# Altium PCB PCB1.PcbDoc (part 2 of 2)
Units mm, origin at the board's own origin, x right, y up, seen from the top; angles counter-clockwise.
Board outline 100 x 100 mm, 2 copper layers (Top Layer, Bottom Layer); 114 components, 82 nets, 496 pads, 121 vias.
Unrouted connection lines stored in the file: 6.
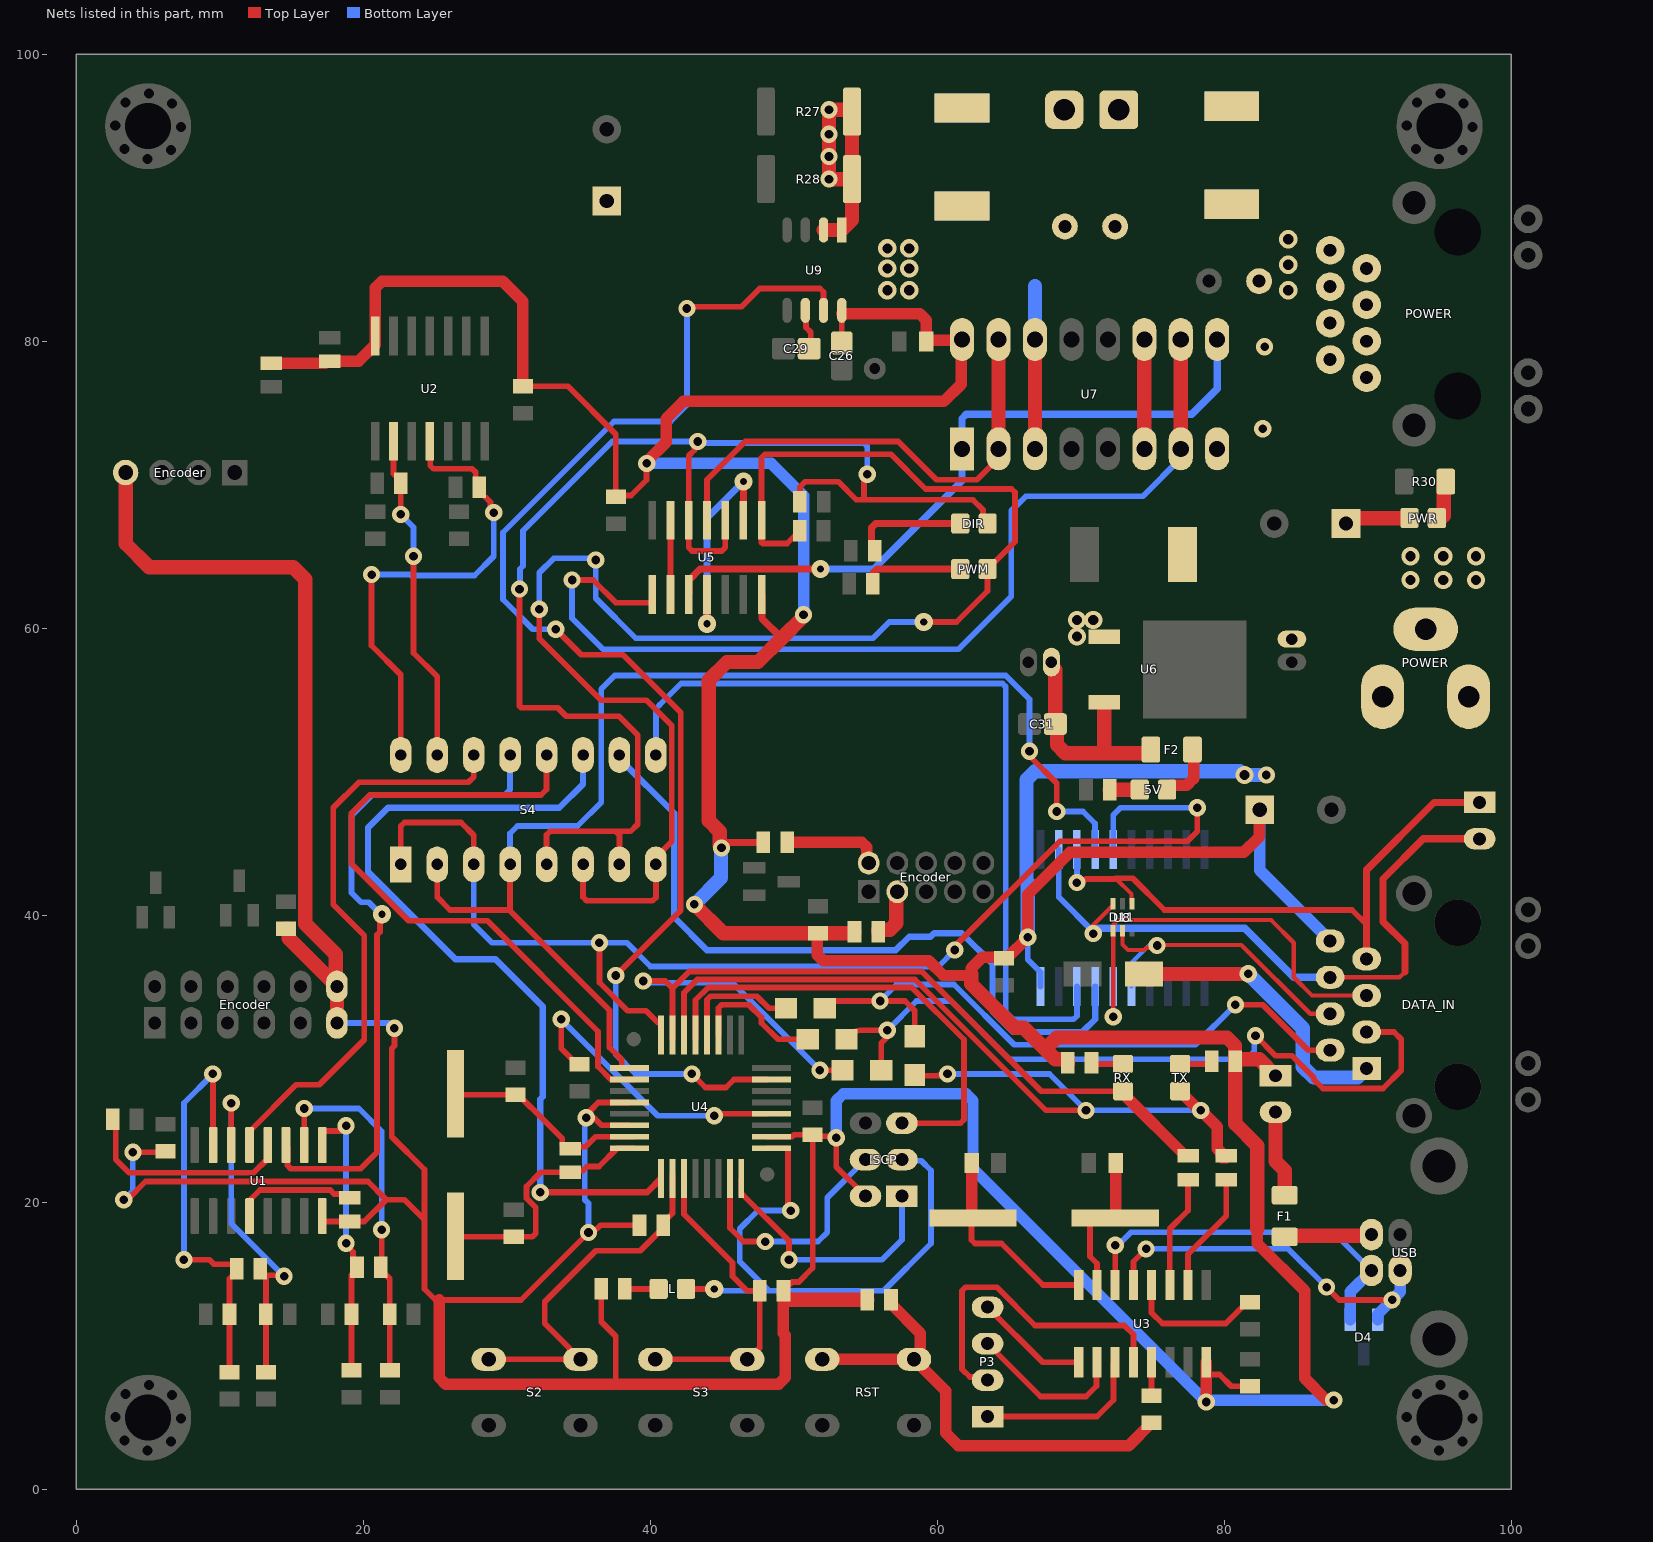
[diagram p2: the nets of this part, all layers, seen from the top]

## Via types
v1: diameter 1.2, hole 0.6, Top Layer to Bottom Layer, 93 vias
v2: diameter 1.27, hole 0.711, Top Layer to Bottom Layer, 22 vias
v3: diameter 1.27, hole 0.5, Top Layer to Bottom Layer, 6 vias

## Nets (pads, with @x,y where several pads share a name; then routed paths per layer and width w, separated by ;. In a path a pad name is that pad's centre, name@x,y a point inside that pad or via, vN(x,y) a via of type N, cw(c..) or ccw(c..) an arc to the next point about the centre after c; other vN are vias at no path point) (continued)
6: 5V.A C1.1 C2.1 C8.1 C12.1 C13.1 C14.1 C21.1 C22.1 C24.1 C25.2 C26.2 DATA_IN.8 Encoder.4@3.429,70.866 Encoder.11 Encoder.12 F2.2 ISCP.2 P4.1 R1.2 R2.1 R3.1 R10.2 R11.2 R13.1 R15.2 R17.1 R18.1 R21.1 R31.1 U1.16 U2.14 U3.16 U4.4 U4.6 U4.18 U5.14 U7.16 U8.20 U9.8 | length 562.9
  Top Layer w0.4: v1(3.302,20.193) 3.556,20.193 4.826,21.463 20.32,21.463 21.59,20.193 ; v1(3.937,23.495) 6.147,23.495 C12.1@6.223,23.571 ; U1.16@17.145,19.05 17.145,18.769 17.245,18.669 R13.1@19.05,18.669 20.066,18.669 21.59,20.193 ; v1(22.164,32.131) 22.164,30.924 21.971,30.731 21.971,24.575 24.257,22.289 24.257,18.796 ; C13.1@31.115,76.886 34.239,76.886 37.592,73.533 C22.1@37.592,69.19 37.666,69.263 38.656,69.263 39.733,70.34 39.733,71.483 v1(39.751,71.501) ; v1@35.433,25.908 v1@35.536,25.908 ; v1(35.536,25.897) v1@35.536,25.908 ; R31.1@36.577,13.97 36.577,11.683 37.592,10.668 37.592,7.332 ; U4.6@38.542,25.371 36.605,25.371 36.068,25.908 v1@35.536,25.908 ; U4.4@38.542,26.971 36.369,26.971 36.086,26.688 36.086,26.663 35.536,26.113 v1@35.536,25.908 ; R18.1@39.243,18.415 36.52,18.415 36.012,17.907 v1(35.687,17.907) 30.988,13.208 25.273,13.208 25.019,13.208 24.257,13.97 24.257,18.796 ; U4.18@48.142,24.571 U4.18@48.442,24.571 49.866,24.571 50.01,24.714 C14.1@51.308,24.714 ; R21.1@49.55,14.293 49.725,14.293 49.891,14.459 50.34,14.459 51.308,15.427 C14.1@51.308,24.714 ; C26.2@53.34,79.894 U9.8@53.34,81.941 ; U9.8@53.34,82.157 U9.8@53.34,82.169 ; ISCP.2@54.991,20.447 52.959,22.479 v1(52.959,24.511) 52.857,24.613 51.41,24.613 C14.1@51.308,24.714 ; U3.16@78.74,8.13 78.858,8.012 79.662,8.012 80.485,7.188 C8.1@81.788,7.188 ; 21.59,20.193 22.86,20.193 24.257,18.796
  Top Layer w0.5: v1@44.942,44.688 v1(44.958,44.704) 45.339,45.085 R1.2@47.879,45.085 ; U5.14@47.752,62.357 47.769,62.34 47.769,60.689 49.149,59.309
  Top Layer w0.8: R15.2@13.589,78.485 17.35,78.485 17.478,78.613 R11.2@17.653,78.613 19.663,78.613 20.828,79.778 U2.14@20.828,80.378 20.828,83.732 21.297,84.201 29.718,84.201 31.115,82.804 C13.1@31.115,76.886 ; 25.273,13.208 25.273,7.801 25.742,7.332 37.592,7.332 48.934,7.332 49.403,7.801 49.403,10.747 49.275,10.875 49.275,13.618 R21.1@49.275,13.843 ; v1(39.751,71.501) 39.751,71.636 41.098,72.983 41.098,74.626 42.291,75.819 60.452,75.819 61.658,77.025 61.658,80.073 C21.1@59.296,80.073 ; C2.1@51.689,38.76 51.688,38.759 51.688,38.703 51.637,38.652 51.637,37.244 52.045,36.836 59.399,36.836 60.421,35.814 62.357,35.814 ; U9.8@53.34,81.941 58.764,81.941 59.233,81.472 C21.1@59.233,80.01 ; 62.357,35.91 62.357,36.322 63.119,37.084 64.465,37.084 64.592,36.957 C25.2@64.643,37.008 64.834,37.008 66.294,38.468 v1(66.294,38.481) 66.294,41.456 69.237,44.399 81.356,44.399 82.423,45.466 82.423,47.331 C24.1@82.463,47.371 ; 5V.A@76.01,48.768 76.01,48.833 76.244,49.068 77.382,49.068 77.851,49.537 77.851,51.488 F2.2@77.777,51.562 ; v1(78.74,6.096) 78.74,8.13 U3.16@78.74,8.862 ; 82.296,18.161 82.296,17.145 85.598,13.843 85.598,7.747 87.122,6.223 v1(87.63,6.223)
  Top Layer w1: Encoder.4@3.28,70.717 Encoder.4@3.429,70.866 3.429,65.913 5.08,64.262 15.113,64.262 15.954,63.421 15.954,39.418 18.07,37.302 Encoder.12@18.07,35.143 ; C1.1@14.605,39.065 14.795,39.065 14.803,39.057 14.803,38.41 Encoder.12@18.07,35.143 ; Encoder.11@18.161,32.512 Encoder.12@18.161,35.052 Encoder.12@18.07,35.143 ; v1(43.069,40.767) 45.077,38.759 C2.1@51.688,38.759 ; v1(44.958,44.704) 44.958,44.758 44.843,44.873 44.843,45.835 44.069,46.609 44.069,56.388 45.339,57.658 47.498,57.658 49.149,59.309 50.673,60.833 v1(50.673,60.96) ; R21.1@49.275,13.618 49.685,13.208 R17.1@55.118,13.208 ; C2.1@51.689,38.76 54.204,38.76 54.229,38.785 R10.2@54.229,38.862 ; 62.357,35.91 62.357,35.814 62.357,35.218 65.407,32.168 66.012,32.168 68.211,29.968 69.064,29.968 69.089,29.943 R3.1@69.089,29.718 ; 67.836,31.006 68.326,31.496 80.186,31.496 80.746,30.936 80.746,29.87 R2.1@80.771,29.845 ; 82.296,18.161 82.296,23.959 80.771,25.484 R2.1@80.771,29.845 ; P4.1@83.566,28.829 82.423,29.972 80.796,29.972 80.771,29.947 R2.1@80.771,29.845
  Bottom Layer w0.4: v1(3.302,20.193) 3.937,20.828 v1(3.937,23.495) ; Encoder.11@18.161,32.512 v1@21.736,32.512 ; v1(35.536,25.897) 35.433,25.794 35.433,20.193 35.687,19.939 v1(35.687,17.907) ; v1(66.294,38.481) 66.294,36.924 67.183,36.035 U8.20@67.183,35.052
  Bottom Layer w0.8: v1(39.751,71.501) 48.426,71.501 50.673,69.254 v1(50.673,60.96) ; v1(52.959,24.511) 52.959,27.09 53.428,27.559 62.015,27.559 62.484,27.09 62.484,22.352 v1(78.74,6.096) 78.867,6.223 v1(87.63,6.223) ; C24.1@82.463,47.371 82.463,43.14 DATA_IN.8@87.376,38.227
  Bottom Layer w1: v1(43.069,40.767) 44.92,42.618 44.92,44.666 v1(44.958,44.704) ; v1(66.294,38.481) 66.294,42.309 66.216,42.387 66.216,49.452 66.802,50.038 81.08,50.038 81.334,49.784 v2(81.407,49.784) v1(82.931,49.784)
A+: C5.1 R6.2 R9.2 U1.1 | length 20.2
  Top Layer w0.4: U1.1@17.145,24 17.145,24.875 17.245,24.975 18.371,24.975 18.602,25.206 18.659,25.206 v1(18.796,25.343) ; v1(18.796,17.154) 18.796,17.037 19.284,16.549 19.284,15.594 19.559,15.319 19.177,14.937 R6.2@19.177,12.192 C5.1@19.177,8.306
  Bottom Layer w0.4: v1(18.796,17.154) v1(18.796,25.343)
A-: C6.1 R7.1 R9.1 U1.2 | length 25.5
  Top Layer w0.4: U1.2@15.875,24 v1(15.875,26.543) ; v1(21.273,18.098) 21.273,15.382 21.209,15.319 21.845,14.683 R7.1@21.845,12.192 C6.1@21.844,8.306 C6.1@21.844,8.306
  Bottom Layer w0.4: v1(15.875,26.543) 19.685,26.543 21.273,24.956 v1(21.273,18.098)
B+: C3.1 R4.2 R8.2 U1.7 | length 30.1
  Top Layer w0.4: v1(7.493,16.002) 9.271,16.002 9.573,15.7 10.901,15.7 11.176,15.425 11.176,15.192 10.667,14.683 R4.2@10.667,12.192 C3.1@10.668,8.179 C3.1@10.668,8.179 ; v1(9.506,28.956) 9.516,28.947 9.516,24.009 U1.7@9.525,24
  Bottom Layer w0.4: v1(7.493,16.002) 7.493,26.924 9.506,28.937 v1(9.506,28.956)
B-: C4.1 R5.2 R8.1 U1.6 | length 25.3
  Top Layer w0.4: U1.6@10.795,24 v1(10.795,26.924) ; R8.1@12.826,15.367 12.826,15.192 R8.1@13.101,14.917 ; C4.1@13.208,8.179 C4.1@13.208,8.179 R5.2@13.209,12.192 13.209,14.809 R8.1@13.101,14.917 ; v1(14.478,14.859) 14.42,14.917 R8.1@13.101,14.917
  Bottom Layer w0.4: v1(10.795,26.924) 10.795,18.542 v1(14.478,14.859)
D: "Dir - Pulse.2" D11.3 DATA_IN.6 U8.2 | length 48
  Top Layer w0.2: D11.3@72.173,40.64 72.248,40.715 D11.3@72.248,40.828
  Top Layer w0.3: v1(70.866,38.735) 70.866,39.333 D11.3@72.173,40.64 ; DATA_IN.6@87.376,35.687 92.202,35.687 92.583,36.068
  Top Layer w0.5: 92.583,36.068 92.583,38.036 91.059,39.56 91.059,42.545 93.853,45.339 97.79,45.339
  Bottom Layer w0.4: U8.2@68.453,44.602 68.453,41.275 70.866,38.862 v1(70.866,38.735)
  Bottom Layer w0.5: v1(70.866,38.735) 71.235,39.104 81.419,39.104 84.836,35.687 DATA_IN.6@87.376,35.687
Data_1: DATA_IN.3 R32.1 R35.1 | length 52.6
  Top Layer w0.4: R32.1@53.674,31.369 54.018,31.713 cw(c54.731,31.003) 54.605,32.001 cw(c54.654,31.604) 54.654,32.004 v1(56.515,32.004) 56.515,31.543 56.087,31.115 R35.1@56.087,29.21 ; v1(82.169,31.623) 83.566,30.226 84.709,30.226 86.233,28.702 86.233,28.575 86.868,27.94 91.059,27.94 92.329,29.21 92.329,31.369 91.821,31.877 DATA_IN.3@89.916,31.877
  Bottom Layer w0.4: v1(56.515,32.004) 58.547,34.036 60.96,34.036 65.024,29.972 81.534,29.972 82.085,30.523 82.085,31.539 v1(82.169,31.623)
Data_2: DATA_IN.2 R33.1 R34.1 | length 44.6
  Top Layer w0.4: R34.1@52.15,33.528 52.658,34.036 v1(56.007,34.036) 57.743,34.036 58.42,33.359 R33.1@58.42,31.576 ; v1(80.772,33.782) 82.677,33.782 85.852,30.607 DATA_IN.2@87.376,30.607
  Bottom Layer w0.4: v1(56.007,34.036) 57.15,35.179 61.167,35.179 65.358,30.988 77.978,30.988 v1(80.772,33.782)
Dir: DIR.A R23.1 S4.5 S4.7 U5.3 U5.5 | length 96.9
  Top Layer w0.4: v1(30.88,62.743) 30.88,54.603 31.007,54.476 33.547,54.476 34.143,53.88 37.814,53.88 39.116,52.578 39.116,46.355 38.619,45.858 37.581,45.858 ; S4.5@32.766,43.561 32.766,45.623 33,45.858 37.581,45.858 ; S4.7@37.846,43.561 37.846,45.593 37.581,45.858 ; v1(43.307,73.025) 43.077,72.795 43.077,72.433 42.672,72.028 42.672,65.639 42.906,65.405 44.978,65.405 45.212,65.639 U5.3@45.212,66.98 ; R23.1@50.42,68.834 50.42,69.851 50.8,70.231 53.086,70.231 54.356,68.961 54.737,68.961 ; v1(55.118,70.739) 54.888,70.509 54.888,69.112 54.737,68.961 ; DIR.A@63.5,67.31 63.172,67.638 63.172,68.273 62.484,68.961 54.737,68.961
  Bottom Layer w0.4: v1(30.88,62.743) 30.922,62.785 30.922,64.143 31.122,64.343 31.122,66.809 37.338,73.025 v1(43.307,73.025) 43.403,72.929 54.884,72.929 55.118,72.695 v1(55.118,70.739)
Dir2: U5.6 U5.9 | length 5.2
  Top Layer w0.4: U5.9@41.402,62.357 U5.6@41.402,67.539
Dir_D: S4.10 U8.17 | length 51.1
  Bottom Layer w0.444: S4.10@37.846,51.181 37.846,50.927 41.656,47.117 41.656,39.871 43.94,37.587 57.109,37.587 58.041,38.519 59.525,38.519 59.77,38.764 61.7,38.764 63.84,36.624 63.84,33.315 65.278,31.877 70.104,31.877 70.993,32.766 U8.17@70.993,35.052
Dir_M: S4.12 U4.2 | length 47.5
  Top Layer w0.4: S4.12@32.766,51.181 32.766,48.768 32.385,48.387 20.447,48.387 19.177,47.117 19.177,43.596 23.149,39.624 28.642,39.624 36.35,31.915 36.35,29.464 37.243,28.571 U4.2@38.842,28.571
En2: U5.2 U5.11 | length 15.7
  Top Layer w0.5: v3(43.942,60.325) U5.11@43.942,62.357 ; U5.2@46.482,67.539 v3(46.482,70.231)
  Bottom Layer w0.5: v3(43.942,60.325) 43.942,67.691 v3(46.482,70.231)
En_A: S4.13 U1.3 | length 47.3
  Top Layer w0.4: U1.3@14.605,24 14.705,23.9 14.705,22.584 14.939,22.35 19.81,22.35 20.955,23.495 20.955,38.653 21.155,38.853 21.155,39.951 v3(21.292,40.088)
  Bottom Layer w0.4: v3(21.292,40.088) 21.212,40.088 20.379,40.921 19.844,40.921 19.177,41.588 19.177,46.939 20.625,48.387 29.845,48.387 30.226,48.768 S4.13@30.226,51.181
En_A_2: R19.2 S4.15 U2.2 | length 24.2
  Top Layer w0.4: U2.2@22.098,73.406 22.098,70.786 22.605,70.279 R19.2@22.605,70.104 v1(22.605,67.946) ; 23.495,64.262 v1(23.495,65.024) 23.495,58.293 25.146,56.642 S4.15@25.146,51.181
  Bottom Layer w0.4: v1(22.605,67.946) 23.495,67.056 v1(23.495,65.024)
En_A_COM: S4.2 S4.4 U4.1 U8.4 | length 87.6
  Top Layer w0.4: S4.2@25.146,43.551 25.146,41.275 26.035,40.386 30.226,40.386 ; S4.4@30.226,43.561 30.226,40.323 37.15,33.398 37.15,30.795 38.008,29.937 38.008,29.371 U4.1@38.842,29.371 ; v1(66.421,51.435) 66.421,51.114 68.326,49.209 v1(68.326,47.244)
  Bottom Layer w0.4: S4.4@30.226,43.561 30.226,45.72 30.734,46.228 34.925,46.228 36.576,47.879 36.576,55.773 37.523,56.72 64.764,56.72 66.421,55.062 v1(66.421,51.435) ; v1(68.326,47.244) 70.151,47.244 70.993,46.402 U8.4@70.993,44.602
En_A_out: D11.4 DATA_IN.5 U8.16 | length 29.9
  Top Layer w0.3: v1(72.263,32.946) 72.255,32.954 72.255,38.92 D11.4@72.248,38.928 72.273,38.953 72.273,39.373 72.578,39.678 83.258,39.678 84.836,38.1 84.836,35.687 86.106,34.417 DATA_IN.5@89.916,34.417
  Bottom Layer w0.2: v1(72.263,32.946) U8.16@72.263,35.052
En_B: S4.14 U1.5 | length 40.9
  Top Layer w0.4: U1.5@12.065,24 12.065,24.95 15.309,28.194 16.926,28.194 20.066,31.334 20.066,38.608 17.907,40.767 17.907,47.498 19.685,49.276 27.305,49.276 27.686,49.657 S4.14@27.686,51.181
En_B_2: R20.2 S4.16 U2.4 | length 33.9
  Top Layer w0.4: v1(20.574,63.754) 20.574,58.801 22.606,56.769 S4.16@22.606,51.181 ; U2.4@24.638,73.038 24.653,73.023 24.653,71.354 24.887,71.12 27.594,71.12 27.828,70.886 27.828,70.067 R20.2@28.066,69.829 ; R20.2@28.066,69.575 28.853,68.788 28.853,68.302 v1(29.083,68.072)
  Bottom Layer w0.4: v1(20.574,63.754) 23.275,63.754 23.336,63.693 27.752,63.693 29.083,65.024 v1@29.083,68.326
En_B_COM: S4.1 S4.3 U4.32 U8.5 | length 89.6
  Top Layer w0.4: S4.1@22.606,43.561 22.606,46.228 22.86,46.482 26.797,46.482 27.686,45.593 S4.3@27.686,43.561 ; v1(36.449,38.1) 36.449,35.326 38.411,33.364 39.699,33.364 40.542,32.521 40.742,32.521 U4.32@40.742,31.371 ; v1(61.214,37.592) 61.214,37.846 68.529,45.161 77.419,45.161 78.105,45.847 v1(78.105,47.498)
  Bottom Layer w0.4: S4.3@27.686,43.561 27.686,39.37 28.956,38.1 v1(36.449,38.1) 38.363,38.1 40.014,36.449 60.071,36.449 v1(61.214,37.592) ; U8.5@72.263,44.602 72.263,46.99 72.771,47.498 v1(78.105,47.498)
En_B_out: D11.5 DATA_IN.4 U8.15 | length 21.8
  Top Layer w0.3: D11.5@72.898,38.928 72.898,37.973 73.279,37.592 74.422,37.592 74.587,37.757 75.164,37.757 v1(75.311,37.904) ; v1@75.311,37.943 81.183,37.943 85.979,33.147 DATA_IN.4@87.376,33.147
  Bottom Layer w0.3: U8.15@73.533,35.052 73.533,36.703 74.918,38.088 75.101,37.904 v1(75.311,37.904)
GND_M: D7.A D8.A R27.1 R28.1 U9.1 U9.2 | length 18.9
  Top Layer w1: U9.2@52.07,87.769 U9.1@53.34,87.769 54.054,88.483 R28.1@54.054,91.313 ; R27.1@54.054,97.028 R27.1@54.054,96.014 ; R28.1@54.054,91.313 v1(52.451,91.313) v1(52.451,96.139) 53.929,96.139 R27.1@54.054,96.014 ; R28.1@54.054,91.313 R27.1@54.054,96.012 R27.1@54.054,96.014
  other v1: 52.451,92.888 52.451,94.437
I_motor: U4.23 U9.7 | length 92.5
  Top Layer w0.4: v1(33.401,59.944) 35.179,58.166 38.1,58.166 42.119,54.147 42.119,40.341 v1(37.592,35.814) ; v1(42.545,82.296) 42.672,82.423 46.355,82.423 47.625,83.693 51.816,83.693 52.07,83.439 U9.7@52.07,82.169 ; v1(42.894,28.958) 43.843,28.01 45.271,28.01 45.832,28.571 U4.23@48.142,28.571
  Bottom Layer w0.4: v1(33.401,59.944) 31.803,59.944 29.73,62.017 29.73,66.687 37.465,74.422 41.402,74.422 42.545,75.565 v1(42.545,82.296) ; v1(37.592,35.814) 37.592,30.321 38.955,28.958 v1(42.894,28.958)
K1: R18.2 S2.2 S2.3 U4.10 | length 25.8
  Top Layer w0.4: S2.3@28.731,9.069 S2.2@35.131,9.069 ; S2.2@35.056,9.069 34.341,9.784 34.341,9.859 32.639,11.561 32.639,13.081 36.195,16.637 39.29,16.637 40.893,18.24 R18.2@40.893,18.415 40.893,18.59 41.542,19.239 U4.10@41.542,21.971
K2: R21.2 S3.2 S3.3 U4.11 | length 22.4
  Top Layer w0.4: S3.3@40.351,9.069 S3.2@46.752,9.069 46.827,9.069 47.625,9.867 R21.2@47.625,13.843 46.736,13.843 45.72,14.859 45.72,15.796 42.342,19.174 U4.11@42.342,21.971
M1: C23.2 D6.A D8.K Motor.2 U7.3 U7.14 | length 12.6
  Top Layer w1: U7.14@66.734,80.205 U7.14@66.802,80.137 U7.3@66.802,72.517 ; Motor.2@68.834,96.139 68.604,95.909 68.616,95.909 Motor.2@69.097,95.428
  Bottom Layer w1: U7.14@66.802,80.137 66.802,83.852 ; Motor.2@68.834,96.139 Motor.2@68.971,96.002
M2: C23.1 D5.A D7.K Motor.F U7.6 U7.11 | length 7.9
  Top Layer w1: U7.6@74.422,72.517 U7.11@74.422,80.137 U7.11@74.49,80.205
  Bottom Layer w1: Motor.F@72.517,96.012 Motor.F@72.644,96.139
Net5V_K: 5V.K R29.2 | length 2.1
  Top Layer w1: R29.2@72.009,48.768 5V.K@74.105,48.768
NetC7_1: C7.1 U3.4 | length 9.7
  Top Layer w0.4: U3.4@74.93,14.252 74.93,12.319 75.692,11.557 80.099,11.557 81.597,13.056 C7.1@81.788,13.056
NetC9_1: C9.1 U3.13 | length 2.4
  Top Layer w0.4: C9.1@74.93,6.528 U3.13@74.93,8.862 U3.13@74.955,8.837
NetC15_2: C15.2 U3.7 X1.1 | length 10.2
  Top Layer w0.4: U3.7@71.12,14.252 71.12,15.748 70.631,16.237 70.631,18.523 71.031,18.923 X1.1@72.39,18.923
  Top Layer w0.8: X1.1@72.39,18.923 72.441,18.974 C15.2@72.441,22.733
NetC16_2: C16.2 U3.8 X1.2 | length 14.1
  Top Layer w0.4: X1.2@62.382,19.025 62.382,17.379 62.617,17.145 64.471,17.145 67.364,14.252 U3.8@69.85,14.252
  Top Layer w0.8: X1.2@62.382,19.025 C16.2@62.382,22.733
NetC17_2: C17.2 U4.20 | length 21
  Top Layer w0.4: v1(33.782,32.766) 33.782,30.745 34.91,29.616 C17.2@35.052,29.616 ; v1(44.45,26.035) 44.586,26.171 U4.20@48.142,26.171
  Bottom Layer w0.4: v1(33.782,32.766) 40.513,26.035 v1(44.45,26.035)
NetC18_1: C18.1 R22.1 U4.7 X2.2 | length 14.5
  Top Layer w0.4: X2.2@26.416,27.559 26.467,27.508 C18.1@30.607,27.508 30.797,27.508 32.673,25.633 33.867,24.439 33.867,24.023 34.142,23.748 R22.1@34.417,23.748 ; R22.1@34.417,23.875 35.306,23.875 35.481,23.875 36.177,24.571 U4.7@38.842,24.571
NetC19_2: C19.2 R22.2 U4.8 X2.1 | length 17.5
  Top Layer w0.4: X2.1@26.416,17.653 26.467,17.602 31.778,17.602 32.013,17.837 32.013,19.65 31.374,20.289 31.374,21.107 32.365,22.098 R22.2@34.417,22.098 ; R22.2@34.848,21.942 35.131,22.225 35.306,22.225 35.581,22.5 36.421,22.5 37.692,23.771 U4.8@38.842,23.771
NetC29_1: C29.1 U9.6 | length 2.9
  Top Layer w0.4: U9.6@50.8,82.169 50.848,82.121 50.848,80.978 51.181,80.645 51.181,79.618 C29.1@51.065,79.502
NetC31_1: C31.1 C32.1 F2.1 U6.3 | length 16.4
  Top Layer w1: C32.1@67.945,57.658 67.945,57.408 68.221,57.132 C31.1@68.221,53.34 68.336,53.225 68.336,51.894 68.922,51.308 71.614,51.308 ; U6.3@71.628,54.864 71.628,51.322 71.614,51.308 ; F2.1@74.877,51.562 74.877,51.458 74.727,51.308 71.614,51.308
NetD4_1: D4.1 U3.6 USB.2 | length 26.2
  Top Layer w0.4: U3.6@72.39,14.252 v1(72.39,17.018)
  Bottom Layer w0.4: v1(72.39,17.018) 72.578,17.018 73.474,17.914 87.598,17.914 USB.2@90.252,15.26
  Bottom Layer w0.8: D4.1@88.773,11.811 88.773,13.781 USB.2@90.252,15.26
NetD4_2: D4.2 U3.5 USB.3 | length 25.9
  Top Layer w0.4: U3.5@73.66,14.252 73.66,15.875 v1(74.549,16.764) ; v1(87.122,14.097) 88.011,13.208 v1(91.69,13.208)
  Bottom Layer w0.4: v1(74.549,16.764) 84.455,16.764 v1(87.122,14.097) ; USB.3@92.252,15.26 USB.3@92.252,15.537
  Bottom Layer w0.8: D4.2@90.673,11.811 90.673,12.191 92.252,13.77 USB.3@92.252,15.26
NetD9_K: D9.K POWER.1@89.916,77.475 POWER.2 POWER.3 POWER.4
  other v2: 92.964,63.373 95.25,63.373 97.536,63.373 92.964,65.024 95.25,65.024 97.536,65.024
NetD10_2: D10.C DATA_IN.1 | length 20.4
  Top Layer w1: D10.C@74.398,35.918 81.638,35.918 v1(81.661,35.941)
  Bottom Layer w1: v1(81.661,35.941) 85.471,32.131 85.471,29.464 86.233,28.702 89.281,28.702 DATA_IN.1@89.916,29.337
NetDIR_K: DIR.K R26.1 | length 8
  Top Layer w0.5: R26.1@55.626,65.405 55.414,65.617 55.414,67.017 55.707,67.31 DIR.K@61.595,67.31
NetEncoder_2: Encoder.2@55.214,43.656 R1.1 | length 6.8
  Top Layer w0.8: R1.1@49.529,45.085 54.745,45.085 55.08,44.75 55.08,43.79 Encoder.2@55.214,43.656
NetEncoder_3: Encoder.3@57.214,41.656 R10.1 | length 3.8
  Top Layer w1: R10.1@55.879,38.862 55.879,38.987 55.904,39.012 56.702,39.012 57.137,39.448 57.137,41.579 Encoder.3@57.214,41.656
NetF1_1: F1.1 P4.2 | length 6.3
  Top Layer w1: P4.2@83.566,26.289 83.566,22.86 84.201,22.225 F1.1@84.201,20.5 F1.1@84.451,20.5
NetF1_2: F1.2 USB.1 | length 6.1
  Top Layer w0.4: USB.1@90.172,17.68 USB.1@90.252,17.76
  Top Layer w1: F1.2@84.201,17.6 84.281,17.68 USB.1@90.172,17.68
NetISCP_1: ISCP.1 U4.16 | length 18.6
  Top Layer w0.4: U4.16@46.342,21.648 46.342,20.521 46.461,20.521 49.657,17.325 v1(49.657,16.002)
  Bottom Layer w0.4: v1(49.657,16.002) 56.134,16.002 57.531,17.399 ISCP.1@57.531,20.447
NetISCP_3: ISCP.3 L.K U4.17 | length 41
  Top Layer w0.4: L.K@42.481,13.97 v3(44.45,13.97) ; U4.17@48.142,23.771 49.592,23.771 49.592,19.623 v1(49.784,19.431)
  Bottom Layer w0.4: v3(44.45,13.97) 44.577,13.843 48.26,13.843 ; v1(49.784,19.431) 47.498,19.431 46.228,18.161 46.228,15.875 48.26,13.843 ; ISCP.3@57.531,22.987 57.611,22.907 58.881,22.907 59.563,22.225 59.563,17.145 56.261,13.843 48.26,13.843
NetISCP_4: ISCP.4 U4.15 | length 17.4
  Top Layer w0.4: U4.15@45.542,21.971 45.542,18.212 46.482,17.272 v1(48.006,17.272)
  Bottom Layer w0.4: v1(48.006,17.272) 51.689,17.272 52.324,17.907 52.324,20.32 ISCP.4@54.991,22.987
NetL_A: L.A R31.2 | length 2.3
  Top Layer w0.4: R31.2@38.354,13.843 38.481,13.97 L.A@40.576,13.97
NetP3_1: P3.1 U3.11 | length 11.9
  Top Layer w0.4: P3.1@63.5,5.08 71.12,5.08 72.272,6.232 72.272,8.745 U3.11@72.39,8.862
NetP3_2: P3.2 U3.12 | length 22.9
  Top Layer w0.4: P3.2@63.5,7.62 63.29,7.83 62.274,7.83 61.722,8.382 61.722,13.843 61.976,14.097 64.135,14.097 66.802,11.43 73.025,11.43 73.66,10.795 U3.12@73.66,8.862
NetP3_3: P3.3 U3.10 | length 11.1
  Top Layer w0.4: P3.3@63.5,10.16 67.183,6.477 70.358,6.477 71.093,7.212 71.093,8.835 U3.10@71.12,8.862
NetP3_4: P3.4 U3.9 | length 7.9
  Top Layer w0.4: P3.4@63.5,12.7 67.338,8.862 U3.9@69.85,8.862
NetPWM_K: PWM.K R25.1 | length 6.3
  Top Layer w0.4: R25.1@55.499,63.119 R25.1@55.626,62.992
  Top Layer w0.5: 55.562,63.881 55.562,63.91 55.787,64.135 PWM.K@61.595,64.135
NetPWR_K: PWR.K R30.1 | length 3
  Top Layer w1: PWR.K@94.805,67.691 95.121,67.691 95.28,67.85 95.28,70.081 R30.1@95.43,70.231
NetR2_2: R2.2 TX.A | length 2
  Top Layer w0.4: TX.A@76.915,29.654 78.805,29.654 R2.2@78.868,29.591
NetR3_2: R3.2 RX.A | length 2.2
  Top Layer w0.4: R3.2@70.739,29.718 70.802,29.654 RX.A@72.936,29.654
NetR12_2: R12.2 U1.4 | length 15.2
  Top Layer w0.4: R12.2@2.54,25.781 2.737,25.584 2.737,22.998 3.672,22.063 12.348,22.063 13.335,23.05 U1.4@13.335,24
NetR13_2: R13.2 U1.12 | length 8.6
  Top Layer w0.4: U1.12@12.065,19.05 12.165,19.15 12.165,20.235 12.793,20.863 17.687,20.863 17.956,20.594 18.775,20.594 R13.2@19.05,20.319
NetR14_2: R14.2 U3.3 | length 7.9
  Top Layer w0.4: U3.3@76.2,14.252 76.2,18.161 77.47,19.431 R14.2@77.47,21.591
NetR16_2: R16.2 U3.2 | length 8.4
  Top Layer w0.4: U3.2@77.47,14.252 77.47,16.383 80.137,19.05 R16.2@80.137,21.565
NetU5_4: U5.4 U7.2 U7.15 | length 34.8
  Top Layer w0.4: U5.4@43.942,66.98 43.942,70.358 46.609,73.025 57.268,73.025 59.935,70.358 62.765,70.358 64.262,71.855 U7.2@64.262,72.517
  Top Layer w1: U7.2@64.262,72.517 U7.15@64.262,80.137
NetU5_8: U5.8 U7.7 U7.10 | length 69.5
  Top Layer w0.4: v1(34.544,63.373) 36.012,63.373 37.587,61.798 U5.8@40.132,61.798
  Top Layer w1: U7.7@76.962,72.517 U7.10@76.962,80.137
  Bottom Layer w0.4: v1(34.544,63.373) 34.544,60.706 36.703,58.547 61.468,58.547 65.151,62.23 65.151,68.199 66.167,69.215 74.322,69.215 76.962,71.855 U7.7@76.962,72.517
NetU5_10: U5.10 U7.1 U7.9 | length 49.3
  Top Layer w0.5: U5.10@42.672,62.357 42.672,63.34 43.467,64.135 v3(51.858,64.135)
  Bottom Layer w0.5: v3(51.858,64.135) 55.574,64.135 61.236,69.798 61.722,70.283 U7.1@61.722,72.517 61.722,74.637 62.015,74.93 77.724,74.93 79.502,76.708 U7.9@79.502,80.137
P: "Dir - Pulse.1" D11.1 DATA_IN.7 U8.3 | length 42.3
  Top Layer w0.3: 72.417,42.591 73.523,41.485 73.523,40.853 D11.1@73.548,40.828
  Top Layer w0.4: v1(69.723,42.291) 69.876,42.444 70.256,42.444 70.357,42.545 72.463,42.545 ; 72.417,42.591 73.614,42.591 75.819,40.386 88.9,40.386 89.916,39.37
  Top Layer w0.5: DATA_IN.7@89.916,36.957 89.916,39.37 89.916,43.18 94.615,47.879 97.79,47.879
  Bottom Layer w0.4: v1(69.723,42.291) U8.3@69.723,44.602
Pwm: PWM.A R24.1 S4.6 S4.8 U5.1 | length 108.8
  Top Layer w0.4: v1(32.258,61.341) 32.258,59.289 36.556,54.991 39.735,54.991 41.486,53.24 41.486,45.161 40.386,44.061 S4.8@40.386,43.561 40.386,41.255 40.152,41.021 35.56,41.021 35.306,41.275 S4.6@35.306,43.561 ; R24.1@50.419,66.802 49.53,65.913 47.835,65.913 47.752,65.996 U5.1@47.752,67.539 47.752,71.902 47.986,72.136 56.769,72.136 59.182,69.723 65.171,69.723 65.405,69.489 65.405,66.04 64,64.635 63.935,64.635 63.5,64.2 PWM.A@63.5,64.135 63.5,62.611 61.341,60.452 v3(59.055,60.452)
  Bottom Layer w0.4: v1(32.258,61.341) 32.258,63.881 33.274,64.897 36.068,64.897 v1(36.195,64.77) 36.195,62.103 38.989,59.309 55.499,59.309 56.642,60.452 v3(59.055,60.452)
Pwm_D: S4.9 U8.18 | length 58.4
  Bottom Layer w0.4: S4.9@40.386,51.181 40.386,54.412 40.64,54.666 42.144,56.17 64.536,56.17 64.77,55.936 64.77,33.274 65.278,32.766 69.489,32.766 69.723,33 U8.18@69.723,35.052
Pwm_M: S4.11 U4.9 | length 59.3
  Top Layer w0.444: v1(32.324,20.701) 39.772,20.701 U4.9@40.742,21.671
  Bottom Layer w0.444: v1(32.324,20.701) 32.324,27.186 32.512,27.374 32.512,33.655 29.21,36.957 26.416,36.957 20.32,43.053 20.32,46.101 21.717,47.498 33.655,47.498 35.306,49.149 S4.11@35.306,51.181
RST: C9.2 ISCP.5 R17.2 RST.2 RST.3 U4.29 | length 66.3
  Top Layer w0.4: U4.29@43.142,31.371 43.142,34.099 44.029,34.986 58.216,34.986 61.849,31.353 61.849,25.761 61.615,25.527 ISCP.5@57.531,25.527
  Top Layer w0.8: RST.3@51.972,9.069 RST.2@58.372,9.069 ; R17.2@56.768,13.208 56.768,12.933 58.815,10.886 58.815,9.512 RST.2@58.372,9.069 ; C9.2@74.93,4.648 73.33,3.048 61.468,3.048 60.579,3.937 60.579,6.862 RST.2@58.372,9.069
RX: R14.1 R35.2 RX.K U4.31 | length 64.1
  Top Layer w0.4: v1(39.497,35.433) 41.034,35.433 41.542,34.925 ; U4.31@41.542,31.371 U4.31@41.542,31.671 41.542,34.925 ; v1(51.816,29.21) R35.2@53.387,29.21 ; RX.K@72.936,27.749 67.246,27.749 58.91,36.086 42.703,36.086 41.542,34.925
  Top Layer w0.8: RX.K@72.936,27.749 73.171,27.515 73.171,27.365 77.295,23.241 R14.1@77.47,23.241
  Bottom Layer w0.4: v1(39.497,35.433) 39.624,35.306 45.72,35.306 v1(51.816,29.21)
SCL: R34.2 U4.28 | length 8.7
  Top Layer w0.4: U4.28@43.942,31.371 U4.28@43.942,31.671 43.942,34.121 44.196,34.375 47.413,34.375 48.26,33.528 R34.2@49.45,33.528
SDA: R32.2 U4.27 | length 9.4
  Top Layer w0.4: U4.27@44.742,31.671 44.742,33.548 44.976,33.782 46.863,33.782 47.752,32.893 47.752,32.512 48.895,31.369 R32.2@50.974,31.369
TX: R16.1 R33.2 TX.K U4.30 | length 62.6
  Top Layer w0.4: U4.30@42.342,31.371 U4.30@42.342,31.671 42.342,34.611 43.267,35.536 58.444,35.536 67.564,26.416 v1(70.358,26.416) ; R33.2@58.42,28.876 58.467,28.829 60.071,28.829 60.083,28.841 60.591,28.841 v1(60.706,28.956)
  Top Layer w0.8: TX.K@76.915,27.749 v1@78.304,26.361 ; v1(78.359,26.416) 79.502,25.273 79.502,23.749 79.787,23.464 79.787,23.189 79.862,23.114 R16.1@80.137,23.114
  Bottom Layer w0.4: v1(60.706,28.956) 67.818,28.956 v1(70.358,26.416) v1(78.359,26.416)
Vm: C20.1 C27.2 C28.1 C30.1 D5.K D6.K POWER.1@91.028,55.245 POWER.5 POWER.6 POWER.7 POWER.8 PWR.A U6.1 U7.8 | length 4.8
  Top Layer w1: U7.8@79.502,72.517 U7.8@79.629,72.39 ; C28.1@88.479,67.31 88.86,67.691 PWR.A@92.9,67.691
  other v1: 82.677,73.914 82.804,79.629
  other v2: 69.723,59.436 69.723,60.579 70.866,60.579 56.515,83.566 58.039,83.566 84.455,83.566 56.515,85.09 58.039,85.09 84.455,85.344 56.515,86.487 58.039,86.487 84.455,87.122
pads on no net: 5V.0 C26.0 C29.0 C31.0 D11.6 DATA_IN.9 DATA_IN.10 DATA_IN.11 DATA_IN.12 DATA_IN.C DATA_IN.D DIR.0 Encoder.7@61.214,41.656 Encoder.8@61.214,43.656 Encoder.9@63.214,41.656 Encoder.10@63.214,43.656 F1.0 F2.0 L.0 POWER.9 POWER.10 POWER.11 POWER.12 POWER.13 PWM.0 PWR.0 R27.0 R28.0 R30.0 RX.0 TX.0 U1.9 U1.10 U1.11 U1.13 U1.14 U1.15 U2.0 U2.5 U2.6 U2.8 U2.9 U2.10 U2.11 U2.12 U2.13 U3.14 U3.15 U4.12 U4.13 U4.14 U4.19 U4.22 U4.24 U4.25 U4.26 U4.F1 U4.F2 U5.12 U5.13 U8.6 U8.7 U8.8 U8.9 U8.11 U8.12 U8.13 U8.14

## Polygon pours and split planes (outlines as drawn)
1 on Bottom Layer "GND_L02_P-001" (solid, pour order 2): 0,100 0.005,100.005 100,100.005 100,0 0,0
1 on Top Layer "GND_L02_P-001" (solid, remove dead copper, pour order 1): 100,100.005 100,0 0,0 0,100

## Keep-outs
Keep-Out Layer:
  lines w0.254: 44.958,47.498 44.958,55.498 63.958,55.498 63.958,47.498 44.958,47.498

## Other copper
Top Layer:
  rectangle net 1: 77.597,82.169 81.026,85.344
  rectangle net 1: 68.072,82.169 81.026,83.312
  rectangle net 1: 80.264,55.499 86.106,58.293
  rectangle net 1: 84.328,45.974 88.773,48.768
  rectangle net 1: 84.328,45.974 86.106,58.293
  rectangle net 6: 81.026,45.974 83.82,52.832
  rectangle net 6: 77.216,50.038 83.82,52.832
  rectangle net Vm: 83.312,82.55 91.821,88.138
  rectangle net NetD9_K: 76.073,61.849 80.137,67.437
  rectangle net Vm: 86.36,66.548 90.932,74.295
  rectangle net Vm: 78.359,70.739 90.932,74.295
  rectangle net 1: 79.121,67.818 82.042,70.231
  rectangle net 1: 80.899,66.04 84.963,70.231
  rectangle net Vm: 68.834,58.674 72.009,61.341
  rectangle net NetD9_K: 84.963,76.2 91.44,80.899
  rectangle net NetD9_K: 94.996,52.832 98.679,65.659
  rectangle net NetD9_K: 76.073,61.976 98.679,65.659
  rectangle net NetD9_K: 91.694,58.293 97.536,64.516
  rectangle net Vm: 55.753,82.804 59.182,87.122
  rectangle net Vm: 35.306,84.201 40.005,91.059
  rectangle net Vm: 35.306,84.201 58.928,86.106
  rectangle net GND_M: 56.896,87.884 64.389,91.694
  rectangle net GND_M: 59.563,85.217 64.389,91.567
  rectangle net GND_M: 54.229,87.884 57.023,98.044
  rectangle net M1: 59.182,93.472 70.358,98.171
  rectangle net GND_M: 59.563,83.947 77.343,86.487
  rectangle net 1: 70.739,67.818 80.899,70.231
  rectangle net Vm: 78.359,70.739 83.82,74.295
  rectangle net 1: 68.072,62.611 71.12,74.295
  rectangle net 1: 68.072,69.85 73.152,82.931
  rectangle net Vm: 81.534,71.247 84.074,85.09
  rectangle net GND_M: 74.295,85.598 82.931,90.932
  rectangle net M2: 71.12,93.472 82.677,98.171
  rectangle net M1: 67.437,86.741 70.358,98.171
  rectangle net M2: 71.12,86.741 73.914,98.171
Bottom Layer:
  rectangle net Vm: 68.834,58.674 89.535,61.341
  rectangle net NetD9_K: 94.996,52.832 98.679,62.357
  rectangle net Vm: 86.36,52.832 91.059,68.58
  rectangle net NetD9_K: 86.36,69.85 98.679,72.39
  rectangle net NetD9_K: 91.694,58.293 98.679,72.39
  rectangle net NetD9_K: 86.36,69.977 90.932,81.026
  rectangle net Vm: 81.915,70.739 84.074,72.771
  rectangle net Vm: 87.249,52.832 93.853,57.785
  rectangle net NetD9_K: 84.963,76.2 91.44,81.153
  rectangle net Vm: 81.534,82.55 91.821,88.265
  rectangle net Vm: 55.753,82.804 59.69,92.71
  rectangle net 1: 35.179,93.167 47.204,98.044
  rectangle net Vm: 78.359,70.739 83.82,74.295
  rectangle net Vm: 81.534,70.739 84.074,88.138
  rectangle net M1: 59.182,93.472 70.358,98.171
  rectangle net 1: 59.309,75.819 68.707,78.232
  rectangle net GND_M: 51.435,86.614 55.118,98.044
  rectangle net Vm: 59.055,89.535 83.058,92.71
  rectangle net M2: 71.12,93.472 82.677,98.171
  rectangle net 1: 46.609,73.279 51.181,98.044
  rectangle net 1: 50.927,73.279 60.071,79.629
  rectangle net Vm: 78.613,85.725 82.931,89.662
  rectangle net 1: 68.072,75.819 73.152,83.312
  rectangle net M1: 65.786,78.74 67.818,88.9
  rectangle net M2: 70.993,85.598 75.438,89.154
  rectangle net M2: 73.406,78.613 75.438,88.773
  rectangle net M1: 65.786,85.598 70.231,89.154
  text "Mobile Robot Driver" at 91.14,0.808 h1

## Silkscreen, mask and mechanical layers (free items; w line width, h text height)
Top Overlay:
  circle w0.4: c95,95 r3.506
  circle w0.4: c5,95 r3.506
  circle w0.4: c95,5 r3.506
  circle w0.4: c5.005,5 r3.506
  lines w0.2: 3.81,31.369 3.683,31.496 3.683,36.068 3.81,36.195 3.937,36.195 ; 19.939,36.195 20.066,36.195 20.193,36.068 20.193,31.75 20.066,31.623 ; 42.672,87.376 43.434,86.614 ; 44.196,87.376 43.434,86.614 ; 44.323,93.98 43.434,93.98 43.434,86.614 ; 44.704,89.789 44.704,97.536 ; 75.057,98.933 86.741,98.933 86.741,96.012 ; 85.979,96.774 86.741,96.012 ; 87.503,96.774 86.741,96.012
  lines w0.254: 0.508,64.008 16.129,64.008 ; 8.001,30.48 8.001,31.242 ; 8.255,72.263 8.255,73.787 12.319,73.787 12.319,72.263 ; 9.652,85.09 29.337,85.09 ; 9.779,92.71 29.21,92.71 ; 9.779,96.647 29.337,96.647 ; 10.541,30.734 10.541,31.242 ; 13.081,30.734 13.081,31.242 ; 15.288,36.306 15.288,38.052 ; 15.336,38.1 19.431,38.1 19.431,36.322 ; 15.748,30.734 15.748,31.242 ; 21.971,58.674 25.781,58.674 ; 22.352,35.433 30.861,35.433 40.513,35.433 ; 27.051,58.674 30.754,58.674 ; 31.496,34.29 31.496,42.164 ; 37.084,58.674 41.402,58.674 ; 49.149,31.75 48.387,31.75 47.752,32.385 47.752,35.687 47.879,35.814 48.133,35.814 62.103,35.814 62.103,28.448 60.96,27.305 59.055,27.305 ; 53.721,17.399 58.928,17.399 ; 55.255,44.783 55.255,45.212 ; 57.137,40.084 57.137,40.513 ; 57.15,44.704 57.15,45.212 ; 59.214,40.164 59.214,40.656 ; 59.214,44.656 59.214,45.371 ; 60.071,40.64 59.817,40.64 59.817,38.862 64.166,38.862 64.214,38.91 64.214,40.656 ; 0.508,44.45 0.508,62.992 0.508,66.929 16.129,66.929 16.129,44.45 0.508,44.45
  text "(If Use IC do not need R27 and R28)" at 37.719,98.06 h1
  text "ACRRL" at 9.525,97.05 h2
  text "Dr.Asemani" at 9.652,95.016 h2
  text "Shiraz University" at 9.652,93.342 h2
  text "Motor" at 65.532,90.948 h1
  text "Designer:" at 9.525,90.929 h2
  text "Mohammad Sabouri" at 9.525,89.178 h2
  text "09360226014" at 9.525,87.527 h2
  text "Mohamadsabory@yahoo.com" at 9.652,85.851 h2
  text "ASC712" at 41.021,84.425 h2
  text "www.acrrl.ir" at 9.652,83.388 h2
  text "74LS14" at 21.971,82.139 h2
  text "L293" at 56.134,73.639 h2
  text "CON 1" at 8.509,72.39 h0.8
  text "74HC04" at 38.989,69.439 h2
  text "+5V" at 2.032,67.963 h1.5
  text "Gnd" at 10.16,67.963 h1.5
  text "B" at 5.588,67.945 h1.5
  text "A" at 8.128,67.945 h1.5
  text "PCB INFO" at 0.508,64.008 h2
  text "CON 1" at 22.098,59.055 h0.8
  text "CON 2" at 26.924,59.055 h0.8
  text "Data_IN" at 37.084,58.928 h0.8
  text "Encoder B" at 22.098,58.42 h0.8 r270
  text "Encoder A" at 24.596,58.42 h0.8 r270
  text "Encoder B" at 27.093,58.42 h0.8 r270
  text "Encoder A" at 29.591,58.42 h0.8 r270
  text "DIR Micro" at 32.258,58.42 h0.8 r270
  text "PWM Micro" at 34.798,58.42 h0.8 r270
  text "PWM Data" at 39.878,58.293 h0.8 r270
  text "DIR Data" at 37.465,58.166 h0.8 r270
  text "Based on Arduino Uno (Mega328) / Input Range: 6-36V DC / Max Motor opration: 36V, 2A / Data IN/Out: Pulse, Direction, Encoder, Vcc 5, GND, I2c or Serial /  / Facilities: / 1- Direct Pulse / Dir / 2- Two Phases Encoder input / 3- Differential Encoder input / 4- Measuring motor Current / 5- Encoder input filter / 6- Protection on input pins and USB port / 7- 5 volt power regulator / 8- I2c or Serial Communication / 9- Encoder output / 10- Encoder Buffer / 11- Input Buffer / 12- Communication Selector" at 0.889,46.101 h1
  text "GND" at 60.175,45.362 h0.7 r90
  text "B" at 56.642,45.339 h1.5
  text "+5V" at 54.968,45.108 h0.7 r90
  text "En B Micro" at 27.178,42.164 h0.8 r270
  text "DIR Motor" at 32.131,42.164 h0.8 r270
  text "PWM Motor" at 34.671,42.164 h0.8 r270
  text "En B Micro" at 22.098,42.037 h0.8 r270
  text "En A Micro" at 24.511,42.037 h0.8 r270
  text "En A Micro" at 29.718,42.037 h0.8 r270
  text "DIR Motor" at 37.338,42.037 h0.8 r270
  text "PWM Motor" at 39.751,42.037 h0.8 r270
  text "OFF / (disconnect)" at 14.955,40.894 h0.7
  text "GND" at 53.825,40.536 h0.7 r90
  text "CON1*" at 60.198,39.243 h0.8
  text "A" at 58.42,37.973 h1.5
  text "+5V" at 57.635,37.869 h0.7 r90
  text "CON 2" at 15.494,36.703 h0.8
  text "Encoder Micro" at 22.733,34.163 h0.8
  text "PWM/DIR Motor" at 32.258,34.036 h0.8
  text "Input select" at 56.261,33.709 h0.7
  text "Gnd" at 0.762,33.165 h1.5
  text "B-" at 11.176,28.448 h1.5 r90
  text "B+" at 8.509,28.321 h1.5 r90
  text "A+" at 13.589,28.321 h1.5 r90
  text "A-" at 16.117,28.194 h1.5 r90
  text "26LS32" at 17.018,26.259 h2
  text "RST" at 58.928,24.783 h1.5
  text "Mega328" at 33.401,19.614 h1.8
  text "Ch340" at 75.438,16.353 h2
  text "DTS" at 65.024,10.35 h0.7
  text "DSR" at 65.024,7.81 h0.7
  text "DSD" at 65.024,5.27 h0.7
  text "RT" at 65.151,2.603 h0.7
  text "DC Motor Driver & Controller" at 15.113,0.437 h4
Bottom Overlay:
  lines w0.2: 91.821,76.708 91.821,80.518 ; 91.821,81.788 91.821,85.344
  lines w0.254: 0.508,64.008 16.129,64.008 ; 12.573,75.565 12.573,98.171 ; 18.415,75.438 18.415,98.044 ; 29.972,75.438 29.972,98.298 ; 0.508,44.45 16.129,44.45 16.129,66.929 0.508,66.929 0.508,62.992 0.508,44.45
  text "ACRRL" at 12.161,98.552 h2.8 r90
  text "Shiraz University" at 17.124,98.425 h2.8 r90
  text "Dr.Asemani" at 14.577,98.298 h2.8 r90
  text "09360226014" at 26.128,98.298 h2.8 r90
  text "Mohamadsabory@yahoo.com" at 28.425,98.298 h2.8 r90
  text "Designer:" at 20.68,98.171 h2.8 r90
  text "Mohammad Sabouri" at 23.334,98.171 h2.8 r90
  text "www.acrrl.ir" at 32.182,98.171 h2.5 r90
  text "Motor" at 72.771,92.347 h1.8
  text "V+" at 94.361,83.185 h1.8
  text "Gnd" at 95.25,78.254 h1.8
  text "POWER_Input / 7-35V" at 95.28,68.965 h1.8
  text "PCB INFO" at 16.129,64.008 h2
  text "POWER_Input / 7-35V" at 88.265,53.34 h1.8
  text "- Encoder Con1: Typical 2 phase Encoder. / - Encoder Con1*: Same Con 1 encoder with Special for DC motor. / - Encoder Con2: 2 Phase ddifferential Encoder with A+,A-,B+,B-. /   / - U9: Current IC : ACS712 (If Use IC do not need R27 and R28) / - Just one encoder can send data to micro ( Do not connect Dip switch for two encoder) / - Just one PWM data can send to motor(Do not connect both PWM data and PWM micro in Dip switch) / - PWM data in Dip switch connect to DATA_IN Port." at 15.875,48.006 h1
  text "74HC541" at 77.293,46.833 h2
  text "www.acrrl.ir" at 14.478,42.494 h2.5
  text "DATA_Input" at 90.932,40.325 h1.8
  text "USB / Mega328 Programing / Arduino Uno" at 89.027,19.812 h1.8
  text "DC Motor Driver & Controller" at 61.214,0.564 h4
Mechanical 1:
  the board outline again, w0.254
